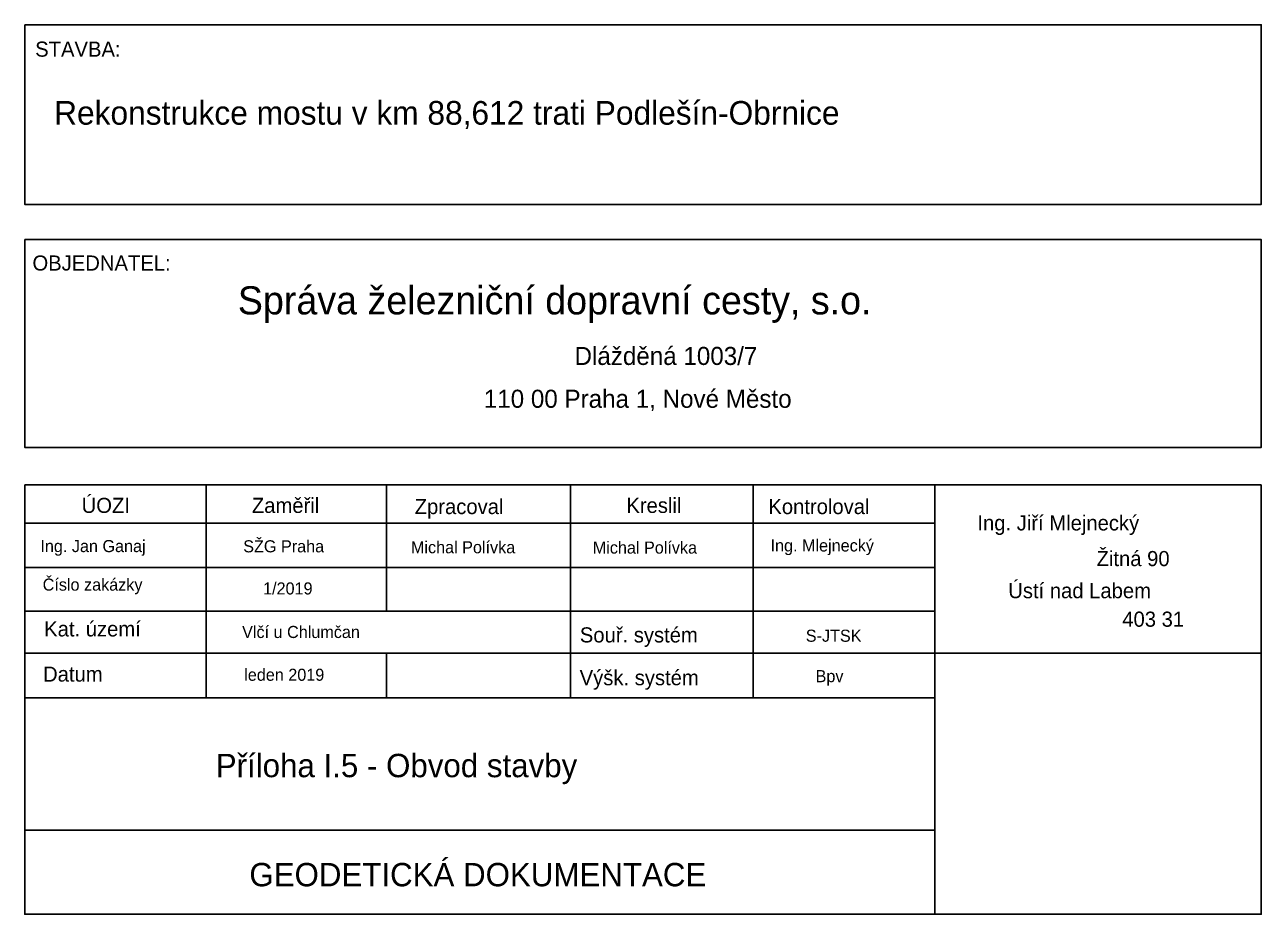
# Model space of a CAD drawing. Extents: x -879530 to -879371, y -1019242 to -1019127.
import ezdxf

# ---------------------------------------------------------------- set-up
doc = ezdxf.new("R2010")
doc.units = 0
doc.layers.add('LEGENDA', color=7, linetype='Continuous')
doc.layers.add('tabulka', color=7, linetype='Continuous')

msp = doc.modelspace()

# ---------------------------------------------------------------- linework, layer by layer
at = {"layer": 'tabulka'}
for p, q in [((-879530.09, -1019186.45), (-879371.44, -1019186.45)), ((-879506.8, -1019186.45), (-879506.8, -1019213.77)), ((-879483.66, -1019186.45), (-879483.66, -1019202.65)), ((-879460.06, -1019186.45), (-879460.06, -1019213.77)), ((-879436.61, -1019186.45), (-879436.61, -1019213.77)), ((-879413.31, -1019241.58), (-879413.31, -1019186.45)), ((-879530.09, -1019191.36), (-879413.31, -1019191.36)), ((-879530.09, -1019197.07), (-879413.31, -1019197.07)), ((-879530.09, -1019202.65), (-879413.31, -1019202.65)), ((-879530.09, -1019208.07), (-879371.44, -1019208.07)), ((-879483.66, -1019208.07), (-879483.66, -1019213.77)), ((-879530.09, -1019213.77), (-879413.31, -1019213.77)), ((-879530.09, -1019230.76), (-879413.31, -1019230.76))]:
    msp.add_line(p, q, dxfattribs=at)
for points in [[(-879530.09, -1019127.36), (-879371.44, -1019127.36), (-879371.44, -1019150.43), (-879530.09, -1019150.43)], [(-879530.09, -1019154.95), (-879371.44, -1019154.95), (-879371.44, -1019181.64), (-879530.09, -1019181.64)]]:
    msp.add_lwpolyline(points, close=True, dxfattribs=at)
msp.add_lwpolyline([(-879371.44, -1019186.45), (-879371.44, -1019241.58), (-879530.09, -1019241.58), (-879530.09, -1019186.45)], dxfattribs=at)

# ---------------------------------------------------------------- texts
at = {"layer": 'LEGENDA'}
msp.add_text('Rekonstrukce mostu v km 88,612 trati Podlešín-Obrnice', height=3.04, dxfattribs=at).set_placement((-879526.32, -1019140.2))
at = {"layer": 'tabulka'}
for s, height, p in [('STAVBA:', 1.94, (-879528.75, -1019131.47)), ('OBJEDNATEL:', 1.94, (-879529.1, -1019158.93)), ('Správa železniční dopravní cesty, s.o.', 3.61, (-879502.75, -1019164.56)), ('Dlážděná 1003/7', 2.32, (-879459.55, -1019171.05)), ('110 00 Praha 1, Nové Město', 2.32, (-879471.19, -1019176.55)), ('ÚOZI', 1.94, (-879522.79, -1019190.05)), ('Zaměřil', 1.94, (-879500.95, -1019190.05)), ('Zpracoval', 1.94, (-879480.06, -1019190.2)), ('Kreslil', 1.94, (-879452.9, -1019190.05)), ('Kontroloval', 1.94, (-879434.68, -1019190.2)), ('Ing. Jiří Mlejnecký', 1.94, (-879407.86, -1019192.3)), ('Ing. Jan Ganaj', 1.552, (-879528.08, -1019195.08)), ('SŽG Praha', 1.552, (-879502.06, -1019195.11)), ('Ing. Mlejnecký', 1.552, (-879434.4, -1019195)), ('Michal Polívka', 1.552, (-879480.54, -1019195.23)), ('Michal Polívka', 1.552, (-879457.21, -1019195.27)), ('Žitná 90', 1.94, (-879392.57, -1019196.88)), ('Číslo zakázky', 1.552, (-879527.79, -1019200.03)), ('1/2019', 1.552, (-879499.51, -1019200.52)), ('Ústí nad Labem', 1.94, (-879403.9, -1019201)), ('403 31', 1.94, (-879389.27, -1019204.66)), ('Kat. území', 1.94, (-879527.6, -1019205.91)), ('Vlčí u Chlumčan', 1.552, (-879502.2, -1019206.11)), ('Souř. systém', 1.94, (-879458.87, -1019206.68)), ('S-JTSK', 1.552, (-879429.88, -1019206.59)), ('Datum', 1.94, (-879527.74, -1019211.71)), ('leden 2019', 1.552, (-879501.93, -1019211.6)), ('Výšk. systém', 1.94, (-879458.89, -1019212.17)), ('Bpv', 1.552, (-879428.62, -1019211.78)), ('Příloha I.5 - Obvod stavby', 3, (-879505.58, -1019223.98)), ('GEODETICKÁ DOKUMENTACE ', 3, (-879501.27, -1019237.99))]:
    msp.add_text(s, height=height, dxfattribs=at).set_placement(p)

doc.saveas('drawing.dxf')
